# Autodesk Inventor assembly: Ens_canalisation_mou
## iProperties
Shininess: 64.0
Length Units: 11269
Angle Units: 11279
Time Units: 11290
Mass Units: 11283
Length Display Precision: 3
Angle Display Precision: 2
Compacted: True
Created: 2008-02
Part Number: Ens_canalisation_mou
Document SubType Name: Assembly
Designer: Pascal
Density: 0.0
Volumn: 0.0
Area: 0.0
PropertySet Name: Model Information
Control State: 0
Master: False
Checked Out: False
DESIGNATION: Ensemble sortie vendange
Author: Pascal
